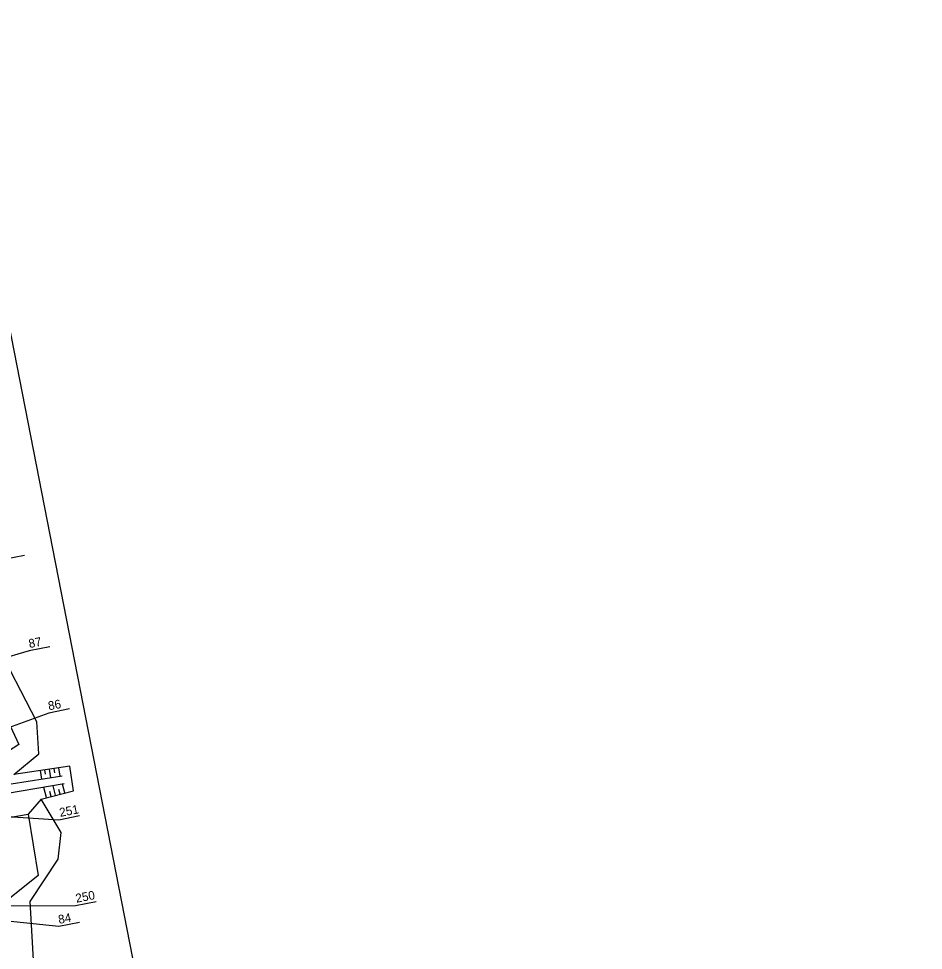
# Model space of a CAD drawing. Extents: x -545846 to -545044, y -1122650 to -1119108.
# Drawn here: x -545486.4 to -545292.2, y -1119578.9 to -1119378.9 of the extents above; entities that cross this region are included whole.
import ezdxf

# ---------------------------------------------------------------- set-up
doc = ezdxf.new("R2010")
doc.units = 0
for name, color, linetype in [('so180602', 7, 'Continuous'), ('Vrstva 10', 7, 'Continuous'), ('Vrstva 62', 7, 'Continuous'), ('Vrstva 63', 7, 'Continuous')]:
    doc.layers.add(name, color=color, linetype=linetype)

msp = doc.modelspace()

# ---------------------------------------------------------------- linework, layer by layer
at = {"layer": 'Vrstva 10'}
msp.add_line((-545554.37, -1119108.31), (-545292.19, -1120447.89), dxfattribs=at)
at = {"layer": 'Vrstva 62'}
for points in [[(-545497.33, -1119511.25), (-545486.34, -1119534.72), (-545495.96, -1119540.92), (-545493.16, -1119551.22), (-545484.39, -1119549.67), (-545482.18, -1119562.89), (-545489.11, -1119568.39), (-545487.95, -1119587.82), (-545483.04, -1119613.89), (-545473.08, -1119650.55), (-545465.95, -1119679.91), (-545460.34, -1119700)], [(-545456.42, -1119700), (-545467.27, -1119650.55), (-545474.74, -1119632.03), (-545476.88, -1119607.3), (-545475.61, -1119597.69), (-545476.4, -1119590.7), (-545482.87, -1119587.28), (-545483.91, -1119568.42), (-545477.93, -1119559.36), (-545477.27, -1119553.64), (-545481.58, -1119546.45), (-545474.62, -1119544.67), (-545475.41, -1119539.39), (-545487.42, -1119541.16), (-545482.06, -1119536.75), (-545482.51, -1119529.89), (-545491.65, -1119512.29)], [(-545481.81, -1119540.33), (-545481.53, -1119542.17)], [(-545480.82, -1119540.19), (-545480.68, -1119541.1)], [(-545479.83, -1119540.04), (-545479.56, -1119541.87)], [(-545478.84, -1119539.9), (-545478.7, -1119540.81)], [(-545477.85, -1119539.75), (-545477.58, -1119541.57)], [(-545476.63, -1119543.2), (-545491.79, -1119545.78)], [(-545491.73, -1119543.73), (-545477.04, -1119541.48)], [(-545476.52, -1119545.15), (-545477.01, -1119543.26)], [(-545476.52, -1119545.15), (-545477.01, -1119543.26)], [(-545480.4, -1119546.15), (-545480.97, -1119543.94)], [(-545479.43, -1119545.9), (-545479.7, -1119544.83)], [(-545478.46, -1119545.65), (-545478.99, -1119543.6)], [(-545477.49, -1119545.4), (-545477.75, -1119544.42)], [(-545481.58, -1119546.45), (-545484.39, -1119549.67)]]:
    msp.add_lwpolyline(points, dxfattribs=at)
at = {"layer": 'Vrstva 63'}
for p, q in [((-545485.17, -1119494.16), (-545489.61, -1119495.02)), ((-545484.16, -1119514.61), (-545513.35, -1119523.17)), ((-545479.71, -1119513.75), (-545484.16, -1119514.61)), ((-545475.51, -1119527.11), (-545479.95, -1119527.98)), ((-545479.95, -1119527.98), (-545532.1, -1119547.23)), ((-545477.79, -1119550.96), (-545505.33, -1119549.21)), ((-545473.35, -1119550.09), (-545477.79, -1119550.96)), ((-545473.35, -1119550.09), (-545477.79, -1119550.96)), ((-545473.35, -1119550.09), (-545477.79, -1119550.96)), ((-545474.19, -1119569.36), (-545526.76, -1119569.55)), ((-545469.75, -1119568.5), (-545474.19, -1119569.36)), ((-545469.75, -1119568.5), (-545474.19, -1119569.36)), ((-545469.75, -1119568.5), (-545474.19, -1119569.36)), ((-545477.78, -1119573.85), (-545500.07, -1119571.55)), ((-545473.34, -1119572.98), (-545477.78, -1119573.85))]:
    msp.add_line(p, q, dxfattribs=at)

# ---------------------------------------------------------------- texts
at = {"layer": 'so180602'}
for s, p in [('87', (-545484.08, -1119514.03)), ('86', (-545479.89, -1119527.4)), ('251', (-545477.47, -1119550.29)), ('250', (-545474, -1119568.73)), ('84', (-545477.72, -1119573.27))]:
    msp.add_text(s, height=1.875, rotation=10.9955, dxfattribs=at).set_placement(p)

doc.saveas('drawing.dxf')
